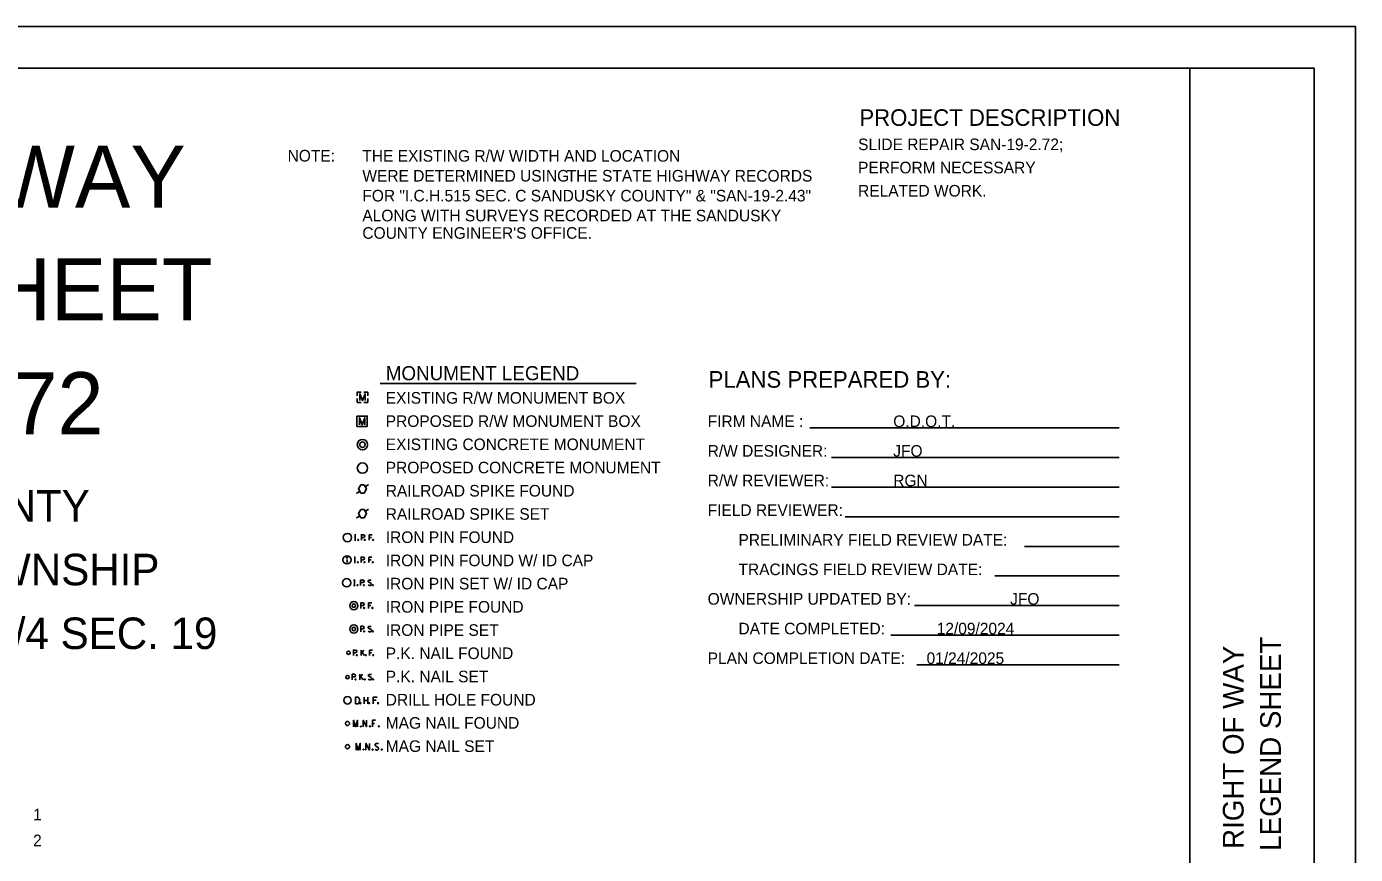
# Model space of a CAD drawing. Extents: x 0 to 34, y 0 to 22.
# Drawn here: x 17.96 to 34, y 12.02 to 22 of the extents above; entities that cross this region are included whole.
import ezdxf

# ---------------------------------------------------------------- set-up
doc = ezdxf.new("R2010")
doc.units = 0
for name, color, linetype in [('SH_Border', 7, 'Continuous'), ('SH_Cut_Line', 7, 'Continuous'), ('SH_Data', 7, 'Continuous'), ('SH_Text', 7, 'Continuous'), ('SV_P_Control_Cells_Set', 7, 'Continuous'), ('SV_X_Control_Cells_Found', 7, 'Continuous')]:
    doc.layers.add(name, color=color, linetype=linetype)

msp = doc.modelspace()

# ---------------------------------------------------------------- linework, layer by layer
at = {"layer": 'SH_Border'}
msp.add_line((32, 0.5), (32, 21.5), dxfattribs=at)
msp.add_lwpolyline([(1.5, 21.5), (33.5, 21.5), (33.5, 0.5), (1.5, 0.5)], close=True, dxfattribs=at)
at = {"layer": 'SH_Cut_Line'}
msp.add_lwpolyline([(0, 0), (34, 0), (34, 22), (0, 22)], close=True, dxfattribs=at)
at = {"layer": 'SH_Text'}
for p, q in [((22.226, 17.697), (25.319, 17.697)), ((22.014, 17.531), (22.014, 17.531)), ((22.01, 17.24), (22.01, 17.24)), ((27.413, 17.16), (31.15, 17.16)), ((27.677, 16.803), (31.15, 16.803)), ((21.981, 16.399), (21.941, 16.369)), ((22.088, 16.479), (22.048, 16.449)), ((27.677, 16.446), (31.15, 16.446)), ((21.981, 16.102), (21.941, 16.072)), ((22.088, 16.182), (22.048, 16.152)), ((27.841, 16.089), (31.15, 16.089)), ((21.916, 15.871), (21.933, 15.871)), ((21.916, 15.871), (21.933, 15.871)), ((21.916, 15.805), (21.933, 15.805)), ((21.924, 15.805), (21.924, 15.871)), ((22.001, 15.839), (22.028, 15.839)), ((22.095, 15.805), (22.095, 15.871)), ((22.095, 15.871), (22.133, 15.871)), ((22.095, 15.839), (22.122, 15.839)), ((30.004, 15.731), (31.15, 15.731)), ((21.828, 15.574), (21.828, 15.537)), ((21.912, 15.602), (21.928, 15.602)), ((21.912, 15.602), (21.928, 15.602)), ((21.92, 15.535), (21.92, 15.602)), ((21.997, 15.57), (22.023, 15.57)), ((22.09, 15.535), (22.09, 15.602)), ((22.09, 15.602), (22.129, 15.602)), ((22.09, 15.57), (22.118, 15.57)), ((21.912, 15.535), (21.928, 15.535)), ((21.907, 15.325), (21.924, 15.325)), ((21.907, 15.325), (21.924, 15.325)), ((21.907, 15.259), (21.924, 15.259)), ((21.916, 15.259), (21.916, 15.325)), ((21.992, 15.294), (22.019, 15.294)), ((22.087, 15.302), (22.117, 15.286)), ((29.647, 15.374), (31.15, 15.374)), ((21.994, 15.018), (22.02, 15.018)), ((22.087, 14.983), (22.087, 15.05)), ((22.087, 15.05), (22.126, 15.05)), ((22.087, 15.017), (22.115, 15.017)), ((28.677, 15.018), (31.15, 15.018)), ((21.994, 14.736), (22.02, 14.736)), ((22.088, 14.745), (22.118, 14.729)), ((28.391, 14.66), (31.15, 14.66)), ((21.905, 14.449), (21.932, 14.449)), ((21.999, 14.415), (21.999, 14.481)), ((21.999, 14.439), (22.031, 14.481)), ((22.009, 14.452), (22.037, 14.415)), ((22.097, 14.415), (22.097, 14.481)), ((22.097, 14.481), (22.136, 14.481)), ((22.097, 14.449), (22.125, 14.449)), ((28.706, 14.303), (31.15, 14.303)), ((21.891, 14.156), (21.918, 14.156)), ((21.984, 14.122), (21.984, 14.188)), ((21.984, 14.146), (22.016, 14.188)), ((21.994, 14.159), (22.022, 14.122)), ((22.09, 14.165), (22.12, 14.149))]:
    msp.add_line(p, q, dxfattribs=at)
for points in [[(21.952, 17.546), (21.952, 17.593), (21.999, 17.593)], [(21.999, 17.468), (21.952, 17.468), (21.952, 17.515)], [(21.984, 17.489), (21.984, 17.572), (22.014, 17.489), (22.045, 17.572), (22.045, 17.489)], [(22.029, 17.593), (22.077, 17.593), (22.077, 17.546)], [(22.077, 17.515), (22.077, 17.468), (22.029, 17.468)], [(21.947, 17.303), (22.072, 17.303), (22.072, 17.178), (21.947, 17.178), (21.947, 17.303)], [(21.979, 17.199), (21.979, 17.282), (22.01, 17.199), (22.041, 17.282), (22.041, 17.199)], [(22.028, 15.871), (22.001, 15.871), (22.001, 15.805)], [(22.023, 15.602), (21.997, 15.602), (21.997, 15.535)], [(22.019, 15.325), (21.992, 15.325), (21.992, 15.259)], [(22.02, 15.05), (21.994, 15.05), (21.994, 14.983)], [(22.02, 14.768), (21.994, 14.768), (21.994, 14.702)], [(21.932, 14.481), (21.905, 14.481), (21.905, 14.415)], [(21.918, 14.188), (21.891, 14.188), (21.891, 14.122)]]:
    msp.add_lwpolyline(points, dxfattribs=at)
for points in [[(21.996, 16.474), (22.033, 16.474), (22.063, 16.424), (22.033, 16.374), (21.996, 16.374), (21.966, 16.424)], [(21.996, 16.177), (22.033, 16.177), (22.063, 16.127), (22.033, 16.077), (21.996, 16.077), (21.966, 16.127)]]:
    msp.add_lwpolyline(points, close=True, dxfattribs=at)
for centre, radius in [((22.014, 16.958), 0.0625), ((22.014, 16.958), 0.0333), ((22.014, 16.676), 0.0625), ((21.833, 15.838), 0.05), ((21.964, 15.809), 0.00583), ((22.041, 15.809), 0.00583), ((22.143, 15.809), 0.00583), ((21.828, 15.569), 0.05), ((21.828, 15.596), 0.00667), ((21.96, 15.54), 0.00583), ((22.037, 15.54), 0.00583), ((22.138, 15.54), 0.00583), ((21.824, 15.292), 0.05), ((21.956, 15.263), 0.00583), ((22.032, 15.263), 0.00583), ((22.139, 15.263), 0.00583), ((21.91, 15.016), 0.05), ((21.91, 15.016), 0.0206), ((22.034, 14.988), 0.00583), ((22.135, 14.988), 0.00583), ((21.91, 14.735), 0.05), ((21.91, 14.735), 0.0208), ((22.034, 14.706), 0.00583), ((22.141, 14.706), 0.00583), ((21.846, 14.448), 0.0207), ((21.946, 14.419), 0.00583), ((22.055, 14.419), 0.00583), ((22.145, 14.419), 0.00583), ((21.833, 14.155), 0.0206), ((21.931, 14.126), 0.00583), ((22.042, 14.126), 0.00583), ((22.142, 14.126), 0.00583)]:
    msp.add_circle(centre, radius, dxfattribs=at)
for centre, radius, start, end in [((22.025, 15.855), 0.0162, 278.8803, 81.1197), ((22.021, 15.586), 0.0162, 278.8803, 81.1197), ((22.017, 15.31), 0.0162, 278.8803, 81.1197), ((22.093, 15.312), 0.0118, 126.2587, 236.3675), ((22.101, 15.287), 0.0276, 223.6695, 304.3963), ((22.103, 15.29), 0.0349, 61.3463, 118.6537), ((22.107, 15.275), 0.0148, 311.4883, 47.9358), ((22.018, 15.034), 0.0162, 278.8803, 81.1197), ((22.018, 14.752), 0.0162, 278.8803, 81.1197), ((22.094, 14.754), 0.0118, 126.2587, 236.3675), ((22.104, 14.733), 0.0349, 61.3463, 118.6537), ((22.103, 14.729), 0.0276, 223.6695, 304.3963), ((22.109, 14.718), 0.0148, 311.4883, 47.9358), ((21.93, 14.465), 0.0162, 278.8803, 81.1197), ((21.915, 14.172), 0.0162, 278.8803, 81.1197), ((22.096, 14.175), 0.0118, 126.2587, 236.3675), ((22.104, 14.15), 0.0276, 223.6695, 304.3963), ((22.106, 14.154), 0.0349, 61.3463, 118.6537), ((22.11, 14.138), 0.0148, 311.4883, 47.9358)]:
    msp.add_arc(centre, radius, start, end, dxfattribs=at)
at = {"layer": 'SV_P_Control_Cells_Set'}
for points in [[(21.937, 13.275), (21.937, 13.355), (21.962, 13.275), (21.987, 13.355), (21.987, 13.275)], [(22.056, 13.275), (22.056, 13.355), (22.097, 13.275), (22.097, 13.355)], [(22.204, 13.349), (22.203, 13.351), (22.202, 13.352), (22.197, 13.354), (22.191, 13.355), (22.186, 13.355), (22.185, 13.355), (22.177, 13.353), (22.171, 13.349), (22.167, 13.344), (22.166, 13.339), (22.166, 13.335), (22.167, 13.33), (22.172, 13.326), (22.202, 13.307), (22.205, 13.305), (22.206, 13.302), (22.207, 13.298), (22.207, 13.294), (22.207, 13.291), (22.206, 13.288), (22.205, 13.285), (22.204, 13.282), (22.203, 13.281), (22.201, 13.279), (22.199, 13.277), (22.197, 13.276), (22.196, 13.276), (22.191, 13.275), (22.183, 13.275), (22.178, 13.276), (22.171, 13.281), (22.166, 13.284)], [(22.025, 13.286), (22.028, 13.286), (22.03, 13.284), (22.031, 13.282), (22.031, 13.279), (22.03, 13.276), (22.028, 13.275), (22.025, 13.275), (22.024, 13.276), (22.022, 13.279), (22.022, 13.282), (22.024, 13.284), (22.025, 13.286)], [(22.136, 13.286), (22.139, 13.286), (22.14, 13.284), (22.142, 13.282), (22.142, 13.279), (22.14, 13.276), (22.139, 13.275), (22.136, 13.275), (22.134, 13.276), (22.133, 13.279), (22.133, 13.282), (22.134, 13.284), (22.136, 13.286)], [(22.245, 13.286), (22.248, 13.286), (22.25, 13.284), (22.251, 13.282), (22.251, 13.279), (22.25, 13.276), (22.248, 13.275), (22.245, 13.275), (22.244, 13.276), (22.242, 13.279), (22.242, 13.282), (22.244, 13.284), (22.245, 13.286)]]:
    msp.add_lwpolyline(points, dxfattribs=at)
msp.add_circle((21.833, 13.315), 0.0249, dxfattribs=at)
at = {"layer": 'SV_X_Control_Cells_Found'}
for p, q in [((22.033, 13.834), (22.033, 13.914)), ((22.033, 13.874), (22.077, 13.874)), ((22.077, 13.834), (22.077, 13.914)), ((22.145, 13.834), (22.145, 13.914)), ((22.145, 13.914), (22.191, 13.914)), ((22.145, 13.875), (22.178, 13.875))]:
    msp.add_line(p, q, dxfattribs=at)
for points in [[(21.959, 13.914), (21.931, 13.914), (21.931, 13.834), (21.959, 13.834)], [(21.905, 13.555), (21.905, 13.635), (21.93, 13.555), (21.954, 13.635), (21.954, 13.555)], [(22.023, 13.555), (22.023, 13.635), (22.064, 13.555), (22.064, 13.635)], [(22.172, 13.635), (22.134, 13.635), (22.134, 13.555)], [(21.993, 13.565), (21.996, 13.565), (21.997, 13.564), (21.999, 13.561), (21.999, 13.558), (21.997, 13.556), (21.996, 13.555), (21.993, 13.555), (21.991, 13.556), (21.989, 13.558), (21.989, 13.561), (21.991, 13.564), (21.993, 13.565)], [(22.104, 13.565), (22.106, 13.565), (22.108, 13.564), (22.11, 13.561), (22.11, 13.558), (22.108, 13.556), (22.106, 13.555), (22.104, 13.555), (22.102, 13.556), (22.1, 13.558), (22.1, 13.561), (22.102, 13.564), (22.104, 13.565)], [(22.134, 13.595), (22.161, 13.595)], [(22.211, 13.565), (22.214, 13.565), (22.215, 13.564), (22.217, 13.561), (22.217, 13.558), (22.215, 13.556), (22.214, 13.555), (22.211, 13.555), (22.209, 13.556), (22.208, 13.558), (22.208, 13.561), (22.209, 13.564), (22.211, 13.565)]]:
    msp.add_lwpolyline(points, dxfattribs=at)
for centre, radius in [((21.833, 13.875), 0.045), ((21.989, 13.84), 0.007), ((22.096, 13.84), 0.007), ((22.203, 13.84), 0.007), ((21.833, 13.595), 0.0249)]:
    msp.add_circle(centre, radius, dxfattribs=at)
msp.add_arc((21.934, 13.874), 0.0474, 302.5148, 57.4852, dxfattribs=at)

# ---------------------------------------------------------------- texts
at = {"layer": 'SH_Data'}
for s, height, p in [('RIGHT OF WAY', 0.75, (12.527, 19.816)), ('LEGEND SHEET', 0.75, (12.458, 18.457)), ('SAN-19-2.72', 0.75, (13.092, 17.082)), ('SANDUSKY COUNTY', 0.38, (13.64, 16.03)), ('GREEN CREEK TOWNSHIP', 0.38, (12.985, 15.262)), ('N.W. 1/4 SEC. 20 & N.E. 1/4 SEC. 19', 0.38, (11.762, 14.493)), ('1', 0.14, (18.038, 12.427)), ('2', 0.14, (18.038, 12.115))]:
    msp.add_text(s, height=height, dxfattribs=at).set_placement(p)
for s, p in [('LEGEND SHEET', (33.1, 12.06)), ('RIGHT OF WAY', (32.65, 12.082))]:
    msp.add_text(s, height=0.25, rotation=90, dxfattribs=at).set_placement(p)
at = {"layer": 'SH_Text'}
for s, height, p in [('PROJECT DESCRIPTION', 0.2, (28.012, 20.803)), ('SLIDE REPAIR SAN-19-2.72;', 0.14, (27.997, 20.51)), ('NOTE:', 0.14, (21.11, 20.373)), ('THE EXISTING R/W WIDTH AND LOCATION', 0.14, (22.013, 20.371)), ('PERFORM NECESSARY', 0.14, (27.997, 20.23)), ('WERE DETERMINED USING ', 0.14, (22.013, 20.131)), ('THE STATE HIGHWAY RECORDS', 0.14, (24.48, 20.131)), ('RELATED WORK.', 0.14, (27.997, 19.95)), ('FOR "I.C.H.515 SEC. C SANDUSKY COUNTY" & "SAN-19-2.43"', 0.14, (22.013, 19.891)), ('ALONG WITH SURVEYS RECORDED AT THE SANDUSKY', 0.14, (22.013, 19.651)), ("COUNTY ENGINEER'S OFFICE.", 0.14, (22.013, 19.441)), ('MONUMENT LEGEND', 0.17, (22.295, 17.735)), ('PLANS PREPARED BY:', 0.2, (26.192, 17.645)), ('EXISTING R/W MONUMENT BOX', 0.14, (22.295, 17.452)), ('PROPOSED R/W MONUMENT BOX', 0.14, (22.295, 17.172)), ('FIRM NAME :', 0.14, (26.181, 17.17)), ('O.D.O.T.', 0.14, (28.421, 17.17)), ('EXISTING CONCRETE MONUMENT', 0.14, (22.295, 16.892)), ('R/W DESIGNER:', 0.14, (26.181, 16.813)), ('JFO', 0.14, (28.421, 16.813)), ('PROPOSED CONCRETE MONUMENT', 0.14, (22.295, 16.612)), ('R/W REVIEWER:', 0.14, (26.181, 16.456)), ('RGN', 0.14, (28.421, 16.456)), ('RAILROAD SPIKE FOUND', 0.14, (22.295, 16.332)), ('FIELD REVIEWER:', 0.14, (26.181, 16.099)), ('RAILROAD SPIKE SET', 0.14, (22.295, 16.052)), ('IRON PIN FOUND', 0.14, (22.295, 15.772)), ('PRELIMINARY FIELD REVIEW DATE:        ', 0.14, (26.553, 15.741)), ('IRON PIN FOUND W/ ID CAP', 0.14, (22.295, 15.492)), ('TRACINGS FIELD REVIEW DATE:', 0.14, (26.553, 15.384)), ('IRON PIN SET W/ ID CAP', 0.14, (22.295, 15.212)), ('OWNERSHIP UPDATED BY:                       JFO', 0.14, (26.181, 15.028)), ('IRON PIPE FOUND', 0.14, (22.295, 14.932)), ('IRON PIPE SET', 0.14, (22.295, 14.652)), ('DATE COMPLETED:            12/09/2024', 0.14, (26.553, 14.67)), ('P.K. NAIL FOUND', 0.14, (22.295, 14.372)), ('PLAN COMPLETION DATE:     01/24/2025', 0.14, (26.181, 14.313)), ('P.K. NAIL SET', 0.14, (22.295, 14.092)), ('DRILL HOLE FOUND', 0.14, (22.295, 13.812)), ('MAG NAIL FOUND', 0.14, (22.295, 13.532)), ('MAG NAIL SET', 0.14, (22.295, 13.252))]:
    msp.add_text(s, height=height, dxfattribs=at).set_placement(p)

doc.saveas('drawing.dxf')
